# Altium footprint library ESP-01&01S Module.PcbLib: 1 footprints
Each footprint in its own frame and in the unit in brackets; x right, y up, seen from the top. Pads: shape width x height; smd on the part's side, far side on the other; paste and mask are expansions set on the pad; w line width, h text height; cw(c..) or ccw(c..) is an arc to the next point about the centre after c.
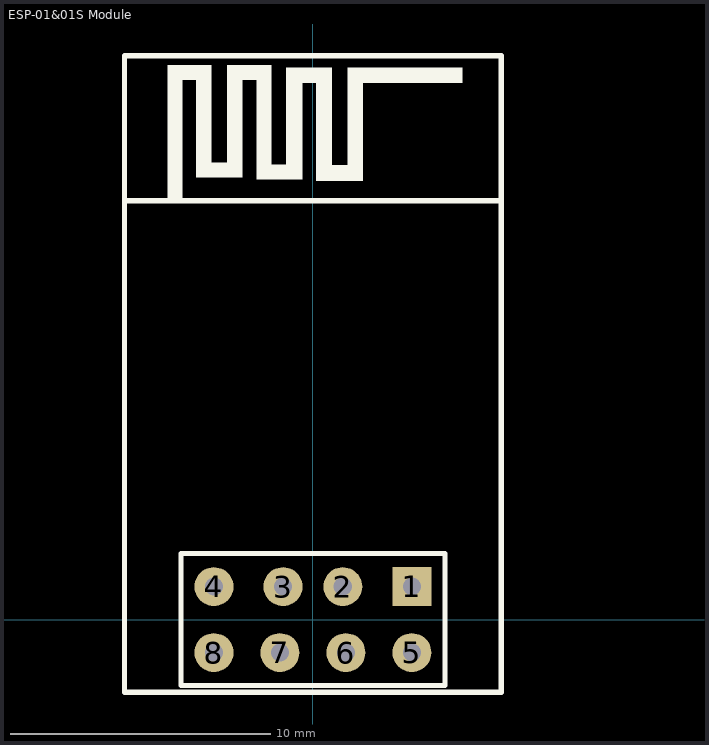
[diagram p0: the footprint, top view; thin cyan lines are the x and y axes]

## ESP-01&01S Module [mm]
pads (8):
  rect 1.5x1.5 hole 0.7: 1(3.81,1.27)
  round 1.5 hole 0.7: 2(1.15,1.27) 3(-1.15,1.27) 4(-3.81,1.27) 5(3.81,-1.27) 6(1.27,-1.27) 7(-1.27,-1.27) 8(-3.81,-1.27)
Top Overlay:
  rectangle: 1.919,20.65 5.755,21.26
  rectangle: 1.335,17.501 1.919,21.26
  rectangle: 0.726,16.891 1.919,17.501
  rectangle: 0.116,16.891 0.726,20.65
  rectangle: -0.392,20.65 0.726,21.26
  rectangle: -1.027,17.526 -0.392,21.26
  rectangle: -1.586,16.942 -0.392,17.526
  rectangle: -2.17,16.942 -1.586,20.777
  rectangle: -2.703,20.777 -1.586,21.361
  rectangle: -3.313,17.602 -2.703,21.361
  rectangle: -3.897,17.018 -2.703,17.602
  rectangle: -4.507,17.018 -3.897,20.777
  rectangle: -5.015,20.777 -3.897,21.361
  rectangle: -5.599,16.129 -5.015,21.361
  lines w0.2: -7.25,16.129 7.25,16.129 ; -7.25,-2.794 -7.25,21.706 7.25,21.706 7.25,-2.794 -7.25,-2.794 ; -5.08,-2.54 5.08,-2.54 5.08,2.54 -5.08,2.54 -5.08,-2.54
